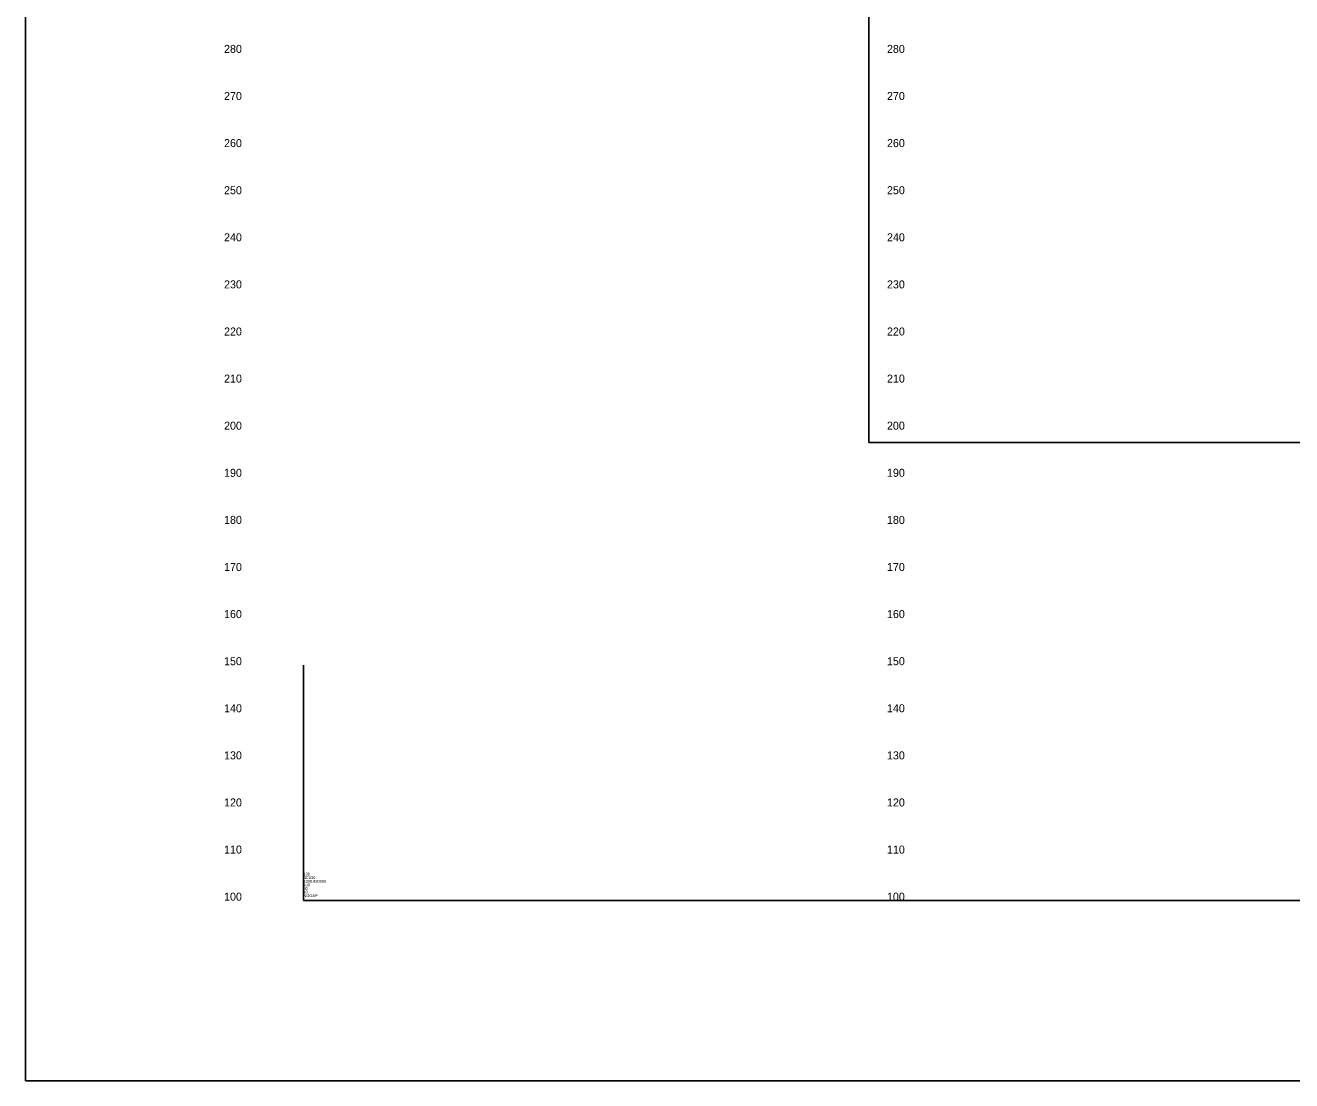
# Model space of a CAD drawing. Extents: x 2230305 to 2233905, y 1078764 to 1080964.
# Drawn here: x 2230305 to 2231649, y 1078764 to 1079884 of the extents above; entities that cross this region are included whole.
import ezdxf

# ---------------------------------------------------------------- set-up
doc = ezdxf.new("R2010")
doc.units = 0
for name, color, linetype in [('RD_DDB_ElevTX', 7, 'Continuous'), ('RD_GPK_Profile_Cell', 7, 'Continuous'), ('RD_SHT_IplotShp', 7, 'Continuous'), ('RD_SHT_ShtClip', 7, 'Continuous')]:
    doc.layers.add(name, color=color, linetype=linetype)

msp = doc.modelspace()

# ---------------------------------------------------------------- linework, layer by layer
at = {"layer": 'RD_GPK_Profile_Cell'}
for q in [(2230600, 1079204.8), (2233609.3, 1078954.8), (2230600, 1078954.8)]:
    msp.add_line((2230600, 1078954.8), q, dxfattribs=at)
at = {"layer": 'RD_SHT_IplotShp'}
msp.add_lwpolyline([(2230304.7, 1078763.7), (2233904.7, 1078763.7), (2233904.7, 1080963.7), (2230304.7, 1080963.7)], close=True, dxfattribs=at)
at = {"layer": 'RD_SHT_ShtClip'}
msp.add_lwpolyline([(2233000.6, 1079441.3), (2231200.6, 1079441.3), (2231200.6, 1080541.3), (2233000.6, 1080541.3)], close=True, dxfattribs=at)

# ---------------------------------------------------------------- texts
at = {"layer": 'RD_DDB_ElevTX'}
for s, p in [('280', (2230515.7, 1079854.8)), ('280', (2231219.7, 1079854.8)), ('270', (2230515.7, 1079804.8)), ('270', (2231219.7, 1079804.8)), ('260', (2230515.7, 1079754.8)), ('260', (2231219.7, 1079754.8)), ('250', (2230515.7, 1079704.8)), ('250', (2231219.7, 1079704.8)), ('240', (2230515.7, 1079654.8)), ('240', (2231219.7, 1079654.8)), ('230', (2230515.7, 1079604.8)), ('230', (2231219.7, 1079604.8)), ('220', (2230515.7, 1079554.8)), ('220', (2231219.7, 1079554.8)), ('210', (2230515.7, 1079504.8)), ('210', (2231219.7, 1079504.8)), ('200', (2230515.7, 1079454.8)), ('200', (2231219.7, 1079454.8)), ('190', (2230515.7, 1079404.8)), ('190', (2231219.7, 1079404.8)), ('180', (2230515.7, 1079354.8)), ('180', (2231219.7, 1079354.8)), ('170', (2230515.7, 1079304.8)), ('170', (2231219.7, 1079304.8)), ('160', (2230515.7, 1079254.8)), ('160', (2231219.7, 1079254.8)), ('150', (2230515.7, 1079204.8)), ('150', (2231219.7, 1079204.8)), ('140', (2230515.7, 1079154.8)), ('140', (2231219.7, 1079154.8)), ('130', (2230515.7, 1079104.8)), ('130', (2231219.7, 1079104.8)), ('120', (2230515.7, 1079054.8)), ('120', (2231219.7, 1079054.8)), ('110', (2230515.7, 1079004.8)), ('110', (2231219.7, 1079004.8)), ('100', (2230515.7, 1078954.8)), ('100', (2231219.7, 1078954.8))]:
    msp.add_text(s, height=8.5, dxfattribs=at).set_placement(p)
at = {"layer": 'RD_GPK_Profile_Cell'}
for s, p in [('SC130', (2230600, 1078977.7)), ('130', (2230600, 1078981.5)), ('50', (2230600, 1078966.2)), ('1390.820000', (2230600, 1078973.8)), ('100', (2230600, 1078970)), ('10', (2230600, 1078962.4)), ('NOGAP', (2230600, 1078958.6))]:
    msp.add_text(s, height=3, dxfattribs=at).set_placement(p)

doc.saveas('drawing.dxf')
